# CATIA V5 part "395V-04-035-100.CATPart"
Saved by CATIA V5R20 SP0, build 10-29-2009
Part number: 395V-04-035-100
Source: Unknown
Property "A": "0.000"
Property "ARTICLENO": "395V-04-035-100"
Property "BOMINFO": "395V-04-035-100"
Property "CODE": "395V-04-035-100"
Property "D": "25.000"
Property "D1": "14.000"
Property "D2": "20.000"
Property "D3": "40.000"
Property "FORM": "A"
Property "L": "100.000"
Property "L1": "12.000"
Property "L2": "38.000"
Property "L3": "30.000"
Property "L4": "8.000"
Property "LINA": "395V-04-035-100"
Property "MAXLOAD": "1250 Kg"
Property "MDW": "2500 Kg"
Property "NB": "395V-04-035-100"
Property "NBSYN": "$CODE."
Property "NN": "395V"
Property "NT": "VDI 3366 Lifting Brackets"
Property "SUPPLIER": "CF"
Property "T": "13.000"
Property "W": "35.000"
Bounding box of the stored display mesh (mm): x -17.5 to 17.5, y 0 to 100, z -17.5 to 17.5
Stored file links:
  C:\Users\Utente\Desktop\3D files 395V\395V-04-035-100.CATPart
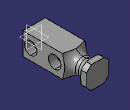
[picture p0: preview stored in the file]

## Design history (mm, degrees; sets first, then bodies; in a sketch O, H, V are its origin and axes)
Body1 "Geometry.1" (main body)
  Solid1 "395V-04-035-100.catpart": solid without history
